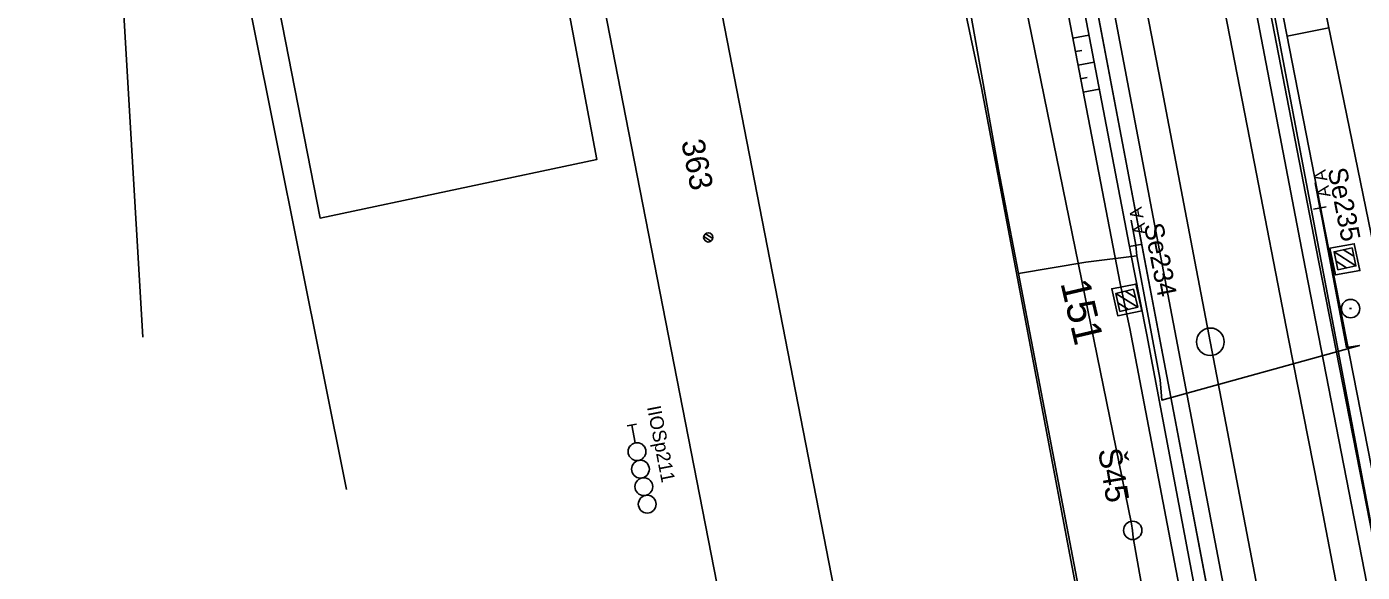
# Model space of a CAD drawing. Extents: x -545967 to -545044, y -1122650 to -1118491.
# Drawn here: x -545804.3 to -545731.6, y -1119096.1 to -1119066.4 of the extents above; entities that cross this region are included whole.
import ezdxf

# ---------------------------------------------------------------- set-up
doc = ezdxf.new("R2010")
doc.units = 0
for name, color, linetype in [('Vrstva 1', 7, 'Continuous'), ('Vrstva 1 - Koleje', 7, 'Continuous'), ('Vrstva 11', 7, 'Continuous'), ('Vrstva 11 - Trakce', 7, 'Continuous'), ('Vrstva 12 - Trakce zaklady', 7, 'Continuous'), ('Vrstva 19 - Staniceni', 7, 'Continuous'), ('Vrstva 26 - silnoproud', 7, 'Continuous'), ('Vrstva 28 - zabzar', 7, 'Continuous'), ('Vrstva 31', 7, 'Continuous'), ('Vrstva 32', 7, 'Continuous'), ('Vrstva 35', 7, 'Continuous'), ('Vrstva 4 - Teren - stezky - prechody - plochy', 7, 'Continuous'), ('Vrstva 43', 7, 'Continuous'), ('Vrstva 44', 7, 'Continuous'), ('Vrstva 48', 7, 'Continuous'), ('Vrstva 49', 7, 'Continuous'), ('Vrstva 6', 7, 'Continuous'), ('Vrstva 6 - Navesti', 7, 'Continuous'), ('Vrstva 62', 7, 'Continuous'), ('Vrstva 7 - Namezniky-vystroj', 7, 'Continuous')]:
    doc.layers.add(name, color=color, linetype=linetype)

msp = doc.modelspace()

# ---------------------------------------------------------------- linework, layer by layer
at = {"layer": 'Vrstva 1'}
for points in [[(-545838.408, -1118714.766), (-545838.264, -1118718.348), (-545837.486, -1118728.28), (-545836.887, -1118733.389), (-545834.73, -1118746.875), (-545830.836, -1118767.188), (-545826.73, -1118788.319), (-545823.138, -1118806.831), (-545818.076, -1118832.894), (-545813.108, -1118858.452), (-545808.531, -1118881.987), (-545803.057, -1118910.121), (-545797.597, -1118938.248), (-545792.143, -1118966.396), (-545787.423, -1118990.652), (-545782.57, -1119015.553), (-545777.212, -1119042.997), (-545771.689, -1119071.297)], [(-545838.408, -1118714.766), (-545838.264, -1118718.348), (-545837.486, -1118728.28), (-545836.887, -1118733.389), (-545834.73, -1118746.875), (-545830.836, -1118767.188), (-545826.73, -1118788.319), (-545823.138, -1118806.831), (-545818.076, -1118832.894), (-545813.108, -1118858.452), (-545808.531, -1118881.987), (-545803.057, -1118910.121), (-545797.597, -1118938.248), (-545792.143, -1118966.396), (-545787.423, -1118990.652), (-545782.57, -1119015.553), (-545777.212, -1119042.997), (-545771.689, -1119071.297)], [(-545771.025, -1119042.195), (-545765.518, -1119070.46), (-545759.655, -1119100.537), (-545754.322, -1119127.883), (-545749.142, -1119154.443), (-545741.38, -1119194.232), (-545736.638, -1119218.552), (-545732.259, -1119241.007)], [(-545771.689, -1119071.297), (-545765.82, -1119101.405), (-545760.255, -1119129.935), (-545755.249, -1119155.634), (-545747.474, -1119195.477), (-545742.774, -1119219.556), (-545738.366, -1119242.197)]]:
    msp.add_lwpolyline(points, dxfattribs=at)
at = {"layer": 'Vrstva 1 - Koleje'}
for points in [[(-545764.382, -1118957.157), (-545762.439, -1118967.113), (-545760.438, -1118977.408), (-545758.491, -1118987.385), (-545756.657, -1118996.796), (-545754.778, -1119006.435), (-545753.329, -1119013.87), (-545751.549, -1119023.001), (-545750.771, -1119027.009), (-545749.861, -1119031.697), (-545747.987, -1119041.333), (-545746.141, -1119050.889), (-545744.24, -1119060.739), (-545742.567, -1119069.426), (-545740.706, -1119079.142), (-545738.925, -1119088.418), (-545738.202, -1119092.228), (-545736.387, -1119101.709)], [(-545760.159, -1118957.414), (-545758.172, -1118967.592), (-545756.196, -1118977.709), (-545754.366, -1118987.085), (-545752.464, -1118996.853), (-545750.606, -1119006.375), (-545748.676, -1119016.269), (-545747.065, -1119024.534), (-545746.698, -1119026.42), (-545745.619, -1119031.955), (-545743.713, -1119041.723), (-545741.694, -1119052.081), (-545739.622, -1119062.694), (-545737.591, -1119073.148), (-545735.605, -1119083.347), (-545733.999, -1119091.546), (-545732.95, -1119096.936)]]:
    msp.add_lwpolyline(points, dxfattribs=at)
at = {"layer": 'Vrstva 11'}
for p, q in [((-545767.073, -1119078.04), (-545767.453, -1119077.786)), ((-545766.966, -1119077.887), (-545767.351, -1119077.629))]:
    msp.add_line(p, q, dxfattribs=at)
msp.add_circle((-545767.208, -1119077.832), 0.25, dxfattribs=at)
at = {"layer": 'Vrstva 11 - Trakce'}
for p, q in [((-545733.123, -1119078.612), (-545731.941, -1119079.381)), ((-545732.604, -1119078.502), (-545732.051, -1119078.862)), ((-545733.017, -1119079.128), (-545732.456, -1119079.493)), ((-545745.015, -1119080.886), (-545743.817, -1119081.628)), ((-545744.499, -1119080.765), (-545743.938, -1119081.112)), ((-545744.898, -1119081.4), (-545744.329, -1119081.752))]:
    msp.add_line(p, q, dxfattribs=at)
for points in [[(-545732.147, -1119078.405), (-545731.94, -1119079.384), (-545732.919, -1119079.591), (-545733.126, -1119078.612)], [(-545744.045, -1119080.658), (-545743.816, -1119081.631), (-545744.789, -1119081.86), (-545745.018, -1119080.887)]]:
    msp.add_lwpolyline(points, close=True, dxfattribs=at)
at = {"layer": 'Vrstva 12 - Trakce zaklady'}
for p, q in [((-545733.349, -1119078.422), (-545732.026, -1119078.177)), ((-545733.055, -1119079.877), (-545731.716, -1119079.641)), ((-545745.232, -1119080.627), (-545743.931, -1119080.373)), ((-545744.911, -1119082.1), (-545743.587, -1119081.836))]:
    msp.add_line(p, q, dxfattribs=at)
for points in [[(-545733.349, -1119078.422), (-545732.026, -1119078.177), (-545731.716, -1119079.641), (-545733.055, -1119079.877), (-545733.349, -1119078.422)], [(-545733.349, -1119078.422), (-545733.349, -1119078.422), (-545733.055, -1119079.877), (-545733.055, -1119079.877)], [(-545743.931, -1119080.373), (-545743.587, -1119081.836), (-545744.911, -1119082.1), (-545745.232, -1119080.627), (-545743.931, -1119080.373)], [(-545745.232, -1119080.627), (-545745.232, -1119080.627), (-545744.911, -1119082.1), (-545744.911, -1119082.1)], [(-545743.931, -1119080.373), (-545743.931, -1119080.373), (-545743.587, -1119081.836), (-545743.587, -1119081.836)]]:
    msp.add_lwpolyline(points, dxfattribs=at)
at = {"layer": 'Vrstva 19 - Staniceni'}
msp.add_circle((-545739.866, -1119083.517), 0.75, dxfattribs=at)
at = {"layer": 'Vrstva 26 - silnoproud'}
msp.add_lwpolyline([(-545800.897, -1118821.514), (-545796.684, -1118843.318), (-545791.187, -1118870.631), (-545788.655, -1118883.96), (-545784.722, -1118904.395), (-545780.641, -1118924.894), (-545776.901, -1118944.085), (-545772.527, -1118967.671), (-545767.712, -1118991.461), (-545763.383, -1119013.326), (-545759.751, -1119031.811), (-545755.576, -1119054.337), (-545752.321, -1119069.685), (-545748.72, -1119088.787), (-545745.498, -1119105.777)], dxfattribs=at)
at = {"layer": 'Vrstva 28 - zabzar'}
msp.add_line((-545743.87, -1119078.84), (-545743.92, -1119078.26), dxfattribs=at)
for points in [[(-545746.9, -1119097.66), (-545750.31, -1119079.79), (-545751.4, -1119074.13), (-545752.97, -1119065.38), (-545755.29, -1119054.49), (-545758.65, -1119036.78), (-545759.72, -1119031.91), (-545755.55, -1119031.19), (-545755.48, -1119031.48)], [(-545750.31, -1119079.79), (-545746.65, -1119079.18), (-545743.87, -1119078.84), (-545742.6, -1119085.59), (-545742.51, -1119086.69), (-545731.75, -1119083.71), (-545732.45, -1119083.82), (-545733.77, -1119076.83), (-545733.9, -1119076.23)]]:
    msp.add_lwpolyline(points, dxfattribs=at)
at = {"layer": 'Vrstva 31'}
msp.add_lwpolyline([(-545746.9, -1119097.66), (-545750.31, -1119079.79), (-545751.4, -1119074.13), (-545752.97, -1119065.38)], dxfattribs=at)
at = {"layer": 'Vrstva 32'}
msp.add_lwpolyline([(-545746.9, -1119097.66), (-545750.31, -1119079.79), (-545751.4, -1119074.13), (-545752.97, -1119065.38), (-545755.29, -1119054.49), (-545758.65, -1119036.78), (-545759.72, -1119031.91), (-545759.89, -1119030.77), (-545763.23, -1119013.33), (-545766.25, -1118997.62), (-545768.86, -1118984.55), (-545771, -1118974.69), (-545771.8, -1118970.9), (-545773.86, -1118959.07), (-545776.3, -1118946.17), (-545780.31, -1118924.98), (-545785.87, -1118897.11), (-545790.99, -1118870.65), (-545796.29, -1118843.25), (-545799.19, -1118827.63)], dxfattribs=at)
at = {"layer": 'Vrstva 35'}
msp.add_line((-545742.51, -1119086.69), (-545731.75, -1119083.71), dxfattribs=at)
at = {"layer": 'Vrstva 4 - Teren - stezky - prechody - plochy'}
for points in [[(-545842.991, -1118523.919), (-545841.705, -1118530.396), (-545836.849, -1118554.447), (-545831.054, -1118584.604), (-545819.351, -1118645.264), (-545811.232, -1118686.911), (-545799.532, -1118746.647), (-545788.535, -1118802.768), (-545777.847, -1118857.696), (-545765.826, -1118919.341), (-545755.98, -1118970.183), (-545745.509, -1119023.121), (-545734.813, -1119078.883), (-545723.148, -1119138.675), (-545711.327, -1119199.256), (-545707.51, -1119218.932), (-545706.355, -1119218.803)], [(-545711.324, -1119247.435), (-545711.901, -1119243.963), (-545720.224, -1119201.665), (-545721.285, -1119195.757), (-545731.546, -1119141.712), (-545737.081, -1119112.42), (-545743.441, -1119079.103), (-545754.278, -1119022.005), (-545764.127, -1118971.243), (-545774.702, -1118917.119), (-545786.098, -1118858.181), (-545797.005, -1118803.413), (-545807.661, -1118749.422), (-545819.911, -1118686.431), (-545828.531, -1118641.36), (-545850.15, -1118530.525), (-545851.156, -1118525.517)], [(-545710.225, -1119247.22), (-545719.004, -1119201.386), (-545730.622, -1119141.385), (-545736.208, -1119112.206), (-545742.564, -1119078.927), (-545753.414, -1119021.814), (-545763.359, -1118970.942), (-545773.922, -1118916.709), (-545785.328, -1118858.188), (-545796.206, -1118802.914), (-545806.845, -1118748.63), (-545819.206, -1118686.191), (-545827.818, -1118641.013), (-545849.345, -1118530.249), (-545850.409, -1118525.371)], [(-545787.709, -1118802.92), (-545777.141, -1118857.583), (-545765.122, -1118918.891), (-545755.123, -1118970.549), (-545744.471, -1119024.933), (-545734.117, -1119078.34), (-545722.331, -1119138.405), (-545711.219, -1119196.145), (-545707.543, -1119214.266), (-545707.412, -1119215.197), (-545706.355, -1119218.803)]]:
    msp.add_lwpolyline(points, dxfattribs=at)
at = {"layer": 'Vrstva 43'}
msp.add_circle((-545744.091, -1119093.784), 0.5, dxfattribs=at)
at = {"layer": 'Vrstva 44'}
for points in [[(-545799.29, -1118815.321), (-545789.933, -1118863.748), (-545789.78, -1118864.001), (-545789.769, -1118864.308), (-545781.742, -1118904.714), (-545781.69, -1118905.058), (-545781.683, -1118905.37), (-545773.843, -1118945.459), (-545773.731, -1118945.723), (-545773.748, -1118946.113), (-545765.823, -1118986.247), (-545765.769, -1118986.707), (-545765.632, -1118987.212), (-545755.037, -1119039.456), (-545755.013, -1119039.882), (-545755.034, -1119040.218), (-545744.158, -1119093.432), (-545744.096, -1119093.785), (-545744.065, -1119094.166), (-545734.822, -1119146.139)], [(-545730.081, -1119098.833), (-545737.375, -1119060.454), (-545745.202, -1119020.613), (-545752.526, -1118984.222)], [(-545739.309, -1119100.743), (-545746.711, -1119061.802), (-545754.214, -1119022.59), (-545761.475, -1118985.918), (-545761.568, -1118985.764)]]:
    msp.add_lwpolyline(points, dxfattribs=at)
at = {"layer": 'Vrstva 48'}
for p, q in [((-545747.354, -1119066.979), (-545746.478, -1119066.811)), ((-545733.412, -1119066.411), (-545735.687, -1119066.878)), ((-545747.213, -1119067.716), (-545746.862, -1119067.648)), ((-545747.071, -1119068.452), (-545746.196, -1119068.284)), ((-545746.929, -1119069.189), (-545746.579, -1119069.122)), ((-545746.787, -1119069.925), (-545745.914, -1119069.757))]:
    msp.add_line(p, q, dxfattribs=at)
at = {"layer": 'Vrstva 49'}
for points in [[(-545839.308, -1118523.198), (-545838.102, -1118529.579), (-545837.4, -1118533.485), (-545832.706, -1118555.695), (-545825.144, -1118594.377), (-545814.251, -1118651.352), (-545808.026, -1118685.152), (-545795.162, -1118750.192), (-545783.943, -1118809.71), (-545774.848, -1118856.951), (-545763.418, -1118915.038), (-545752.928, -1118968.655), (-545741.707, -1119025.946), (-545730.219, -1119081.986), (-545719.001, -1119141.326), (-545708.857, -1119196.833), (-545704.642, -1119214.146)], [(-545785.57, -1118809.023), (-545776.461, -1118857.744), (-545776.223, -1118859.028), (-545764.986, -1118916.441), (-545764.658, -1118917.886), (-545754.446, -1118970.66), (-545754.175, -1118971.989), (-545744.319, -1119022.631), (-545744.059, -1119023.95), (-545733.435, -1119078.425), (-545721.625, -1119138.52), (-545721.391, -1119139.742), (-545710.151, -1119197.125), (-545709.969, -1119198.727), (-545706.792, -1119214.135), (-545707.412, -1119215.197), (-545706.355, -1119218.803), (-545705.856, -1119218.828), (-545705.109, -1119218.756), (-545703.505, -1119218.63), (-545703.071, -1119219.321), (-545701.68, -1119223.926)], [(-545712.345, -1119247.635), (-545712.918, -1119244.626), (-545721.552, -1119201.108), (-545732.642, -1119141.942), (-545733.194, -1119140.665), (-545738.437, -1119113.17), (-545744.258, -1119082.787), (-545744.781, -1119080.348), (-545754.155, -1119031.651), (-545755.213, -1119026.18), (-545765.268, -1118974.147), (-545765.5, -1118972.759), (-545775.821, -1118920.177), (-545776.085, -1118918.771), (-545787.25, -1118861.285), (-545787.565, -1118859.78), (-545796.822, -1118811.001)], [(-545711.324, -1119247.435), (-545711.901, -1119243.963), (-545720.224, -1119201.665), (-545721.285, -1119195.757), (-545721.943, -1119195.521), (-545732.082, -1119141.82), (-545732.265, -1119140.515), (-545737.739, -1119112.717), (-545743.315, -1119083.132), (-545744.039, -1119079.561), (-545753.263, -1119031.334), (-545754.002, -1119028.935), (-545754.148, -1119025.929), (-545754.487, -1119024.319), (-545754.825, -1119024.298), (-545764.544, -1118973.992), (-545764.787, -1118972.577), (-545775.108, -1118920.03), (-545775.396, -1118918.541), (-545786.585, -1118861.093), (-545786.924, -1118859.548), (-545796.323, -1118810.897)]]:
    msp.add_lwpolyline(points, dxfattribs=at)
at = {"layer": 'Vrstva 6'}
for p, q in [((-545771.124, -1119088.002), (-545771.615, -1119088.097)), ((-545771.18, -1119089.021), (-545771.369, -1119088.05))]:
    msp.add_line(p, q, dxfattribs=at)
for centre in [(-545771.087, -1119089.498), (-545770.901, -1119090.451), (-545770.715, -1119091.404), (-545770.53, -1119092.357)]:
    msp.add_circle(centre, 0.486, dxfattribs=at)
at = {"layer": 'Vrstva 6 - Navesti'}
for p, q in [((-545734.165, -1119074.869), (-545733.9, -1119076.23)), ((-545734.244, -1119076.297), (-545733.556, -1119076.163)), ((-545744.18, -1119076.899), (-545743.92, -1119078.26)), ((-545744.264, -1119078.326), (-545743.576, -1119078.194))]:
    msp.add_line(p, q, dxfattribs=at)
at = {"layer": 'Vrstva 62'}
for points in [[(-545831.331, -1118868.059), (-545823.578, -1118887.986), (-545813.29, -1118951.467), (-545805.4, -1118996.869), (-545793.319, -1119059.595), (-545786.903, -1119091.551)], [(-545774.893, -1119065.04), (-545773.283, -1119073.594), (-545788.35, -1119076.781), (-545809.854, -1118967.05), (-545794.565, -1118964.478), (-545793.279, -1118970.053)], [(-545797.993, -1119083.258), (-545799.475, -1119058.284), (-545807.351, -1119014.429)]]:
    msp.add_lwpolyline(points, dxfattribs=at)
at = {"layer": 'Vrstva 7 - Namezniky-vystroj'}
msp.add_line((-545732.278, -1119081.708), (-545732.178, -1119081.708), dxfattribs=at)
msp.add_circle((-545732.228, -1119081.708), 0.5, dxfattribs=at)

# ---------------------------------------------------------------- texts
at = {"layer": 'Vrstva 11'}
msp.add_text('363', height=1.25, rotation=281.16142, dxfattribs=at).set_placement((-545768.684, -1119072.61))
at = {"layer": 'Vrstva 11 - Trakce'}
msp.add_text('151', height=1.6, rotation=283.23179, dxfattribs=at).set_placement((-545748.036, -1119080.312))
at = {"layer": 'Vrstva 43'}
msp.add_text('Š45', height=1.25, rotation=279.31701, dxfattribs=at).set_placement((-545745.984, -1119089.408))
at = {"layer": 'Vrstva 6'}
msp.add_text('IIOSp211', height=0.75, rotation=281.04299, dxfattribs=at).set_placement((-545770.547, -1119087.069))
at = {"layer": 'Vrstva 6 - Navesti'}
for s, height, rotation, p in [('  A A ', 0.7, 101.00666, (-545733.213, -1119076.096)), ('Se235', 1.05, 281.12428, (-545733.482, -1119074.139)), ('  A A ', 0.7, 100.82715, (-545743.232, -1119078.129)), ('Se234', 1.05, 281.12428, (-545743.489, -1119077.155))]:
    msp.add_text(s, height=height, rotation=rotation, dxfattribs=at).set_placement(p)

doc.saveas('drawing.dxf')
